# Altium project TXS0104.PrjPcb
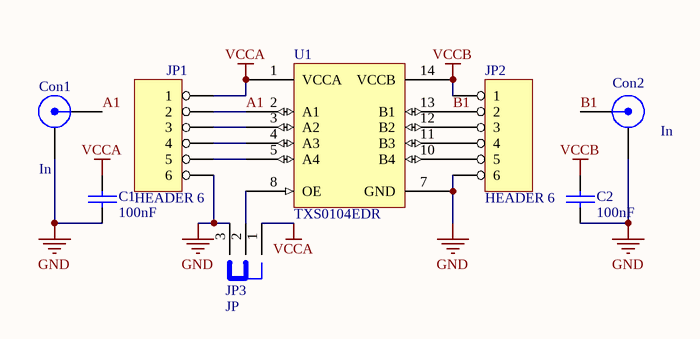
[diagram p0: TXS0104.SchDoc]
1 sheet, 8 parts. Net scope: global (net labels, ports and power ports of the same name join across sheets).
Board file: TXS0104.PcbDoc

## Sheet TXS0104.SchDoc
size A4

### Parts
C1  100nF  [0603]
C2  100nF  [0603]
Con1  In  [SMB_90]
Con2  In  [SMB_90]
JP1  HEADER 6  [SIP-6]
JP2  HEADER 6  [SIP-6]
JP3  JP  [sip-3]
U1  TXS0104EDR  [SO14]

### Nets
GND: C1.2 C2.2 Con1.2(GND) Con2.2(GND) JP1.6 JP2.6 JP3.3 U1.7(GND)
VCCA: C1.1 JP1.1 JP3.1 U1.1(VCCA)
VCCB: C2.1 JP2.1 U1.14(VCCB)
A1: Con1.1(IN) JP1.2 U1.2(A1)
B1: Con2.1(IN) JP2.2 U1.13(B1)
NetJP1_3: JP1.3 U1.3(A2)
NetJP1_4: JP1.4 U1.4(A3)
NetJP1_5: JP1.5 U1.5(A4)
NetJP2_3: JP2.3 U1.12(B2)
NetJP2_4: JP2.4 U1.11(B3)
NetJP2_5: JP2.5 U1.10(B4)
NetJP3_2: JP3.2 U1.8(OE)

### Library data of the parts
C1 C2 = CAP: Capacitor
Con1 Con2 = SMB
JP3 = JP: Jumper
U1 = TXS0104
